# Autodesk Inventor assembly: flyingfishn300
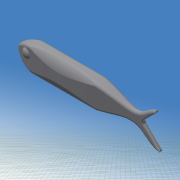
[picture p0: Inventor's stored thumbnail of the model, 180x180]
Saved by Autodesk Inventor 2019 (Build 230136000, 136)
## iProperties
Created: 2021-05
Part Number: flyingfishn300
Material: 一般
Document SubType Name: Assembly
Designer: kikut
Author: kikut
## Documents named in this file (2)
- F:\openFOAM\flyingfish\flyingfish15\oversetmesh\CAD\flyingfishn300.iam
- F:\openFOAM\flyingfish\flyingfish15\oversetmesh\CAD\flyingfish.ipt
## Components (1 placed, 1 different names)
1. flyingfish:1 — フラッシュ:1
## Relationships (1: Flush 1)
- フラッシュ:1 [Flush]: flyingfish:1
